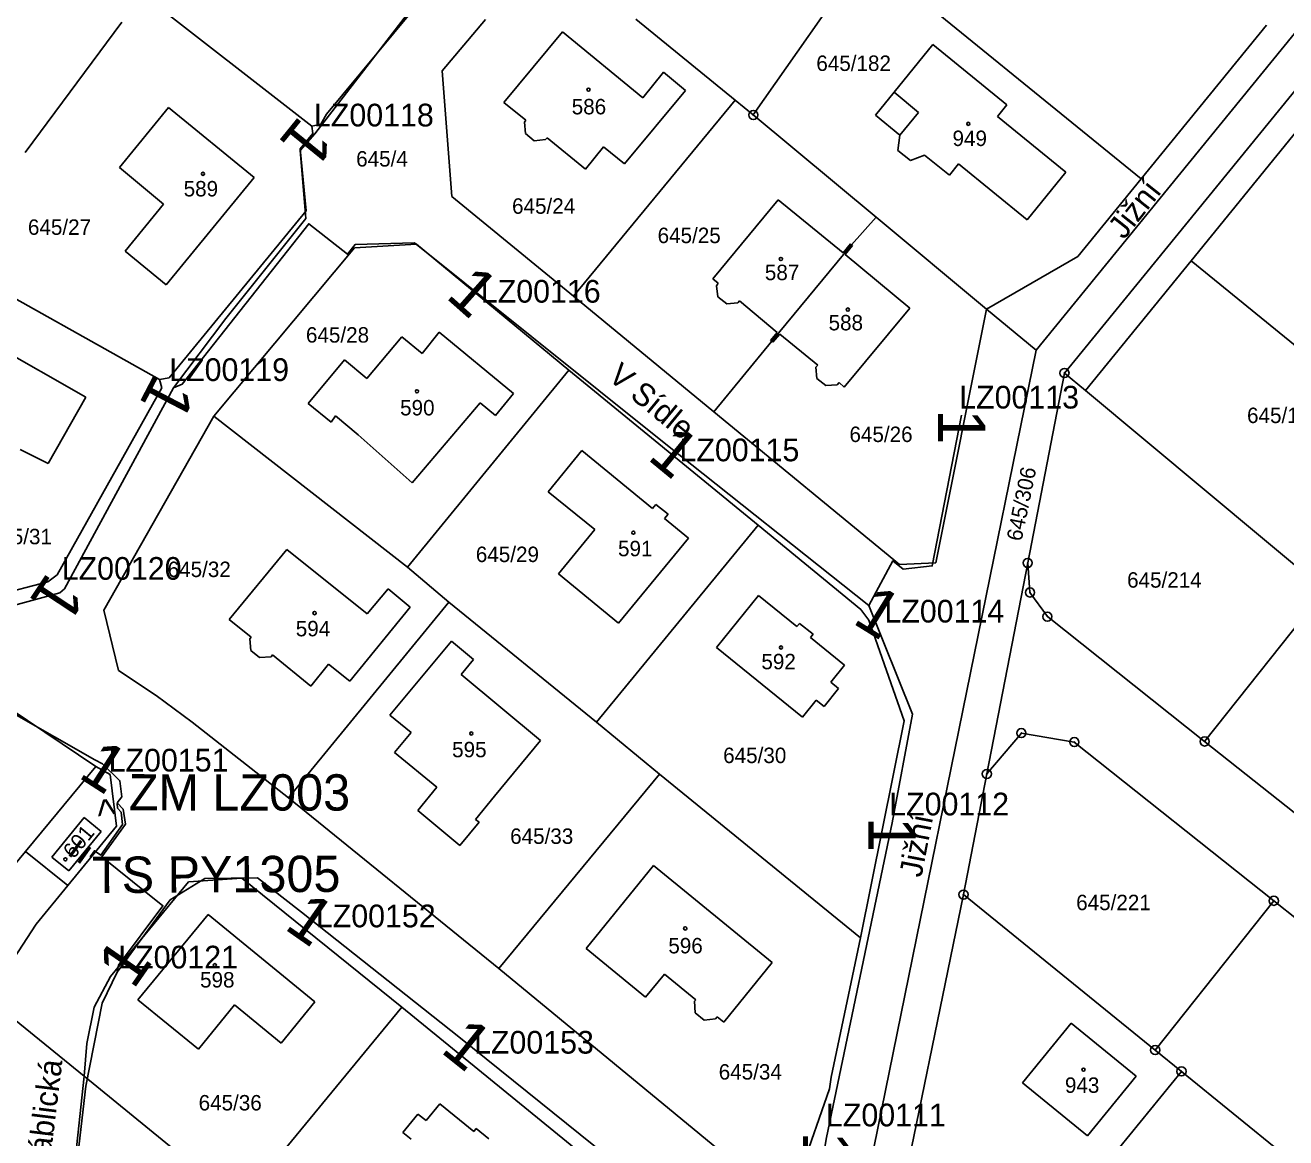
# Model space of a CAD drawing. Extents: x -738131 to -734179, y -1033447 to -1030078.
# Drawn here: x -735880.3 to -735741.5, y -1032698.6 to -1032576 of the extents above; entities that cross this region are included whole.
import ezdxf

# ---------------------------------------------------------------- set-up
doc = ezdxf.new("R2010")
doc.units = 0
for name, color, linetype in [('ftf_2010', 7, 'Continuous'), ('ftf_2060', 7, 'Continuous'), ('ftf_3010', 7, 'Continuous'), ('ftf_3010_ftf_3010_gtda_3015_gtda_3015_1', 7, 'Continuous'), ('ftf_3150', 7, 'Continuous'), ('ftf_3150_ftf_3150_gtda_3155_gtda_3155_1', 7, 'Continuous'), ('ftf_3160', 7, 'Continuous'), ('ftf_3160_ftf_3160_gtda_3165_gtda_3165_1', 7, 'Continuous'), ('ftf_nu', 7, 'Continuous'), ('Vrstva 1', 7, 'Continuous'), ('Vrstva 2', 7, 'Continuous'), ('Vrstva 4', 7, 'Continuous'), ('Vrstva 5', 7, 'Continuous'), ('Vrstva 8', 7, 'Continuous')]:
    doc.layers.add(name, color=color, linetype=linetype)

msp = doc.modelspace()

# ---------------------------------------------------------------- linework, layer by layer
at = {"layer": 'ftf_2010'}
for points in [[(-735833.85, -1032569.08), (-735848.46, -1032588)], [(-735864.01, -1032615.98), (-735858.25, -1032608.32), (-735849.42, -1032597.31), (-735850.04, -1032589.82), (-735848.46, -1032588)], [(-735864.01, -1032615.98), (-735863.04, -1032615.57), (-735849.11, -1032597.9), (-735844.85, -1032601.26), (-735844.01, -1032600.2), (-735837.47, -1032600), (-735831.94, -1032604.46)], [(-735831.94, -1032604.46), (-735809.79, -1032622.16)], [(-735876.03, -1032638.12), (-735864.01, -1032615.98)], [(-735777.21, -1032618.97), (-735780.45, -1032635.59), (-735783.63, -1032635.93), (-735784.8, -1032635.04), (-735787.44, -1032639.95)], [(-735809.79, -1032622.16), (-735787.44, -1032639.95)], [(-735899.61, -1032641.58), (-735899.03, -1032641.38), (-735886.29, -1032648.56), (-735883.11, -1032640.33), (-735876.51, -1032638.56), (-735876.03, -1032638.12)], [(-735787.44, -1032639.95), (-735782.6, -1032651.92), (-735784.87, -1032663.88)], [(-735899.61, -1032641.58), (-735872.69, -1032656.96)], [(-735872.69, -1032656.96), (-735871.81, -1032657.37), (-735869.91, -1032659.24), (-735869.7, -1032661.03), (-735870.21, -1032661.69)], [(-735870.21, -1032661.69), (-735869.54, -1032662.38), (-735869.3, -1032664.04), (-735871.9, -1032667.64), (-735868.54, -1032670.33), (-735865.18, -1032673.02), (-735870.05, -1032679.55), (-735870.2, -1032680.32)], [(-735792.09, -1032698.53), (-735784.87, -1032663.88)], [(-735870.2, -1032680.32), (-735864.37, -1032672.38), (-735860.55, -1032670), (-735854.75, -1032669.95), (-735849.92, -1032673.73)], [(-735832.6, -1032687.44), (-735849.92, -1032673.73)], [(-735870.2, -1032680.32), (-735871.88, -1032683.75), (-735873.65, -1032692.87), (-735875.34, -1032707.51), (-735877.04, -1032718.13)], [(-735813.21, -1032703.05), (-735832.6, -1032687.44)], [(-735792.09, -1032698.53), (-735792.3, -1032699.81), (-735782.31, -1032701.83), (-735783.9, -1032709.89), (-735780.53, -1032712.49)]]:
    msp.add_lwpolyline(points, dxfattribs=at)
at = {"layer": 'ftf_2060'}
msp.add_lwpolyline([(-735870.22, -1032661.74), (-735870.17, -1032662.25), (-735869.79, -1032662.71), (-735869.62, -1032664.07), (-735872.02, -1032667.44), (-735872.71, -1032666.96), (-735873.19, -1032667.63)], dxfattribs=at)
at = {"layer": 'Vrstva 1'}
for points in [[(-735700.24, -1032527.51), (-735768.99, -1032611.83)], [(-735765.88, -1032614.34), (-735697.13, -1032530.02)], [(-735787.81, -1032568.23), (-735800.15, -1032585.92)], [(-735787.81, -1032568.23), (-735757.44, -1032592.96)], [(-735834.19, -1032570.19), (-735847.14, -1032585.83)], [(-735867.41, -1032572.61), (-735848.77, -1032587.14)], [(-735829.66, -1032575.39), (-735834.43, -1032581.05)], [(-735802.16, -1032584.28), (-735813.08, -1032575.37)], [(-735869.69, -1032575.68), (-735880.36, -1032590.05)], [(-735821.16, -1032576.77), (-735827.63, -1032584.55)], [(-735812.32, -1032584.03), (-735821.16, -1032576.77)], [(-735743.64, -1032576.01), (-735757.44, -1032592.96)], [(-735784.64, -1032583.41), (-735780.38, -1032578.16)], [(-735780.38, -1032578.16), (-735772.24, -1032584.8)], [(-735834.43, -1032581.05), (-735833.35, -1032594.91)], [(-735810.05, -1032581.21), (-735812.32, -1032584.03)], [(-735810.05, -1032581.21), (-735807.61, -1032583.24)], [(-735807.61, -1032583.24), (-735814.32, -1032591.3)], [(-735786.69, -1032585.94), (-735784.64, -1032583.41)], [(-735869.97, -1032591.69), (-735864.55, -1032585.08)], [(-735864.55, -1032585.08), (-735855.12, -1032592.82)], [(-735827.63, -1032584.55), (-735825.19, -1032586.49)], [(-735802.16, -1032584.28), (-735819.96, -1032605.86)], [(-735800.15, -1032585.92), (-735802.16, -1032584.28)], [(-735772.24, -1032584.8), (-735773.27, -1032586.07)], [(-735847.79, -1032586.92), (-735847.14, -1032585.83)], [(-735825.19, -1032586.49), (-735825.35, -1032586.71)], [(-735800.15, -1032585.92), (-735786.61, -1032597.19)], [(-735784.02, -1032588.13), (-735786.69, -1032585.94)], [(-735773.27, -1032586.07), (-735765.72, -1032592.23)], [(-735850.05, -1032589.63), (-735848.68, -1032587.96)], [(-735848.77, -1032587.14), (-735847.79, -1032586.92)], [(-735848.68, -1032587.96), (-735848.77, -1032587.14)], [(-735825.35, -1032586.71), (-735825.25, -1032587.96)], [(-735825.25, -1032587.96), (-735824.28, -1032588.76)], [(-735751.92, -1032601.97), (-735740.24, -1032587.63)], [(-735824.28, -1032588.76), (-735823.04, -1032588.63)], [(-735823.04, -1032588.63), (-735822.84, -1032588.43)], [(-735818.65, -1032591.89), (-735822.84, -1032588.43)], [(-735816.66, -1032589.42), (-735818.65, -1032591.89)], [(-735814.32, -1032591.3), (-735816.66, -1032589.42)], [(-735784.25, -1032589.82), (-735784.02, -1032588.13)], [(-735849.38, -1032596.47), (-735850.05, -1032589.63)], [(-735782.85, -1032590.93), (-735784.25, -1032589.82)], [(-735781.29, -1032590.33), (-735782.85, -1032590.93)], [(-735778.56, -1032592.54), (-735781.29, -1032590.33)], [(-735865.12, -1032595.75), (-735869.97, -1032591.69)], [(-735777.55, -1032591.29), (-735778.56, -1032592.54)], [(-735770, -1032597.48), (-735777.55, -1032591.29)], [(-735765.72, -1032592.23), (-735770, -1032597.48)], [(-735855.12, -1032592.82), (-735864.81, -1032604.64)], [(-735757.44, -1032592.96), (-735764.4, -1032601.49)], [(-735819.96, -1032605.86), (-735833.35, -1032594.91)], [(-735869.34, -1032600.92), (-735865.12, -1032595.75)], [(-735797.41, -1032595.25), (-735804.61, -1032603.96)], [(-735790.25, -1032601.12), (-735797.41, -1032595.25)], [(-735864.48, -1032614.86), (-735849.38, -1032596.47)], [(-735789.33, -1032600.21), (-735786.61, -1032597.19)], [(-735786.61, -1032597.19), (-735774.46, -1032607.29)], [(-735844.06, -1032600.56), (-735859.56, -1032619.1)], [(-735837.26, -1032600.15), (-735844.06, -1032600.56)], [(-735820.48, -1032614.02), (-735837.26, -1032600.15)], [(-735798.12, -1032610.84), (-735789.33, -1032600.21)], [(-735789.44, -1032600.11), (-735790.25, -1032601.12)], [(-735789.23, -1032600.31), (-735790.05, -1032601.29)], [(-735789.33, -1032600.21), (-735789.44, -1032600.11)], [(-735789.33, -1032600.21), (-735789.23, -1032600.31)], [(-735864.81, -1032604.64), (-735869.34, -1032600.92)], [(-735790.05, -1032601.29), (-735782.92, -1032607.19)], [(-735774.46, -1032607.29), (-735764.4, -1032601.49)], [(-735751.92, -1032601.97), (-735763.57, -1032616.26)], [(-735751.92, -1032601.97), (-735718.51, -1032629.19)], [(-735865.54, -1032615.06), (-735887.57, -1032602.71)], [(-735804.61, -1032603.96), (-735804.01, -1032604.46)], [(-735804.01, -1032604.46), (-735804.21, -1032604.72)], [(-735804.21, -1032604.72), (-735804.06, -1032605.93)], [(-735804.48, -1032618.62), (-735819.96, -1032605.86)], [(-735804.06, -1032605.93), (-735803.08, -1032606.73)], [(-735803.08, -1032606.73), (-735801.85, -1032606.61)], [(-735801.67, -1032606.39), (-735801.85, -1032606.61)], [(-735801.67, -1032606.39), (-735797.52, -1032609.87)], [(-735782.92, -1032607.19), (-735790.13, -1032615.89)], [(-735774.46, -1032607.29), (-735780.06, -1032635.26)], [(-735774.46, -1032607.29), (-735768.99, -1032611.83)], [(-735836.63, -1032612.19), (-735834.74, -1032609.85)], [(-735834.74, -1032609.85), (-735826.55, -1032616.58)], [(-735797.52, -1032609.87), (-735798.24, -1032610.76)], [(-735798, -1032610.93), (-735797.24, -1032610.05)], [(-735793.06, -1032613.47), (-735797.24, -1032610.05)], [(-735883.86, -1032611.2), (-735873.65, -1032616.99)], [(-735838.86, -1032610.35), (-735842.7, -1032614.94)], [(-735838.86, -1032610.35), (-735836.63, -1032612.19)], [(-735798.12, -1032610.84), (-735804.48, -1032618.62)], [(-735798.24, -1032610.76), (-735798.12, -1032610.84)], [(-735798.12, -1032610.84), (-735798, -1032610.93)], [(-735845.19, -1032612.87), (-735849.17, -1032617.68)], [(-735842.7, -1032614.94), (-735845.19, -1032612.87)], [(-735768.99, -1032611.83), (-735797.93, -1032753.98)], [(-735820.48, -1032614.02), (-735838.24, -1032635.71)], [(-735799.63, -1032631.11), (-735820.48, -1032614.02)], [(-735793.26, -1032613.7), (-735793.06, -1032613.47)], [(-735793.14, -1032614.94), (-735793.26, -1032613.7)], [(-735769.93, -1032635.25), (-735765.88, -1032614.34)], [(-735765.88, -1032614.34), (-735763.57, -1032616.26)], [(-735865.54, -1032615.06), (-735864.48, -1032614.86)], [(-735865.29, -1032615.98), (-735865.54, -1032615.06)], [(-735792.15, -1032615.73), (-735793.14, -1032614.94)], [(-735790.91, -1032615.63), (-735792.15, -1032615.73)], [(-735790.71, -1032615.4), (-735790.91, -1032615.63)], [(-735790.13, -1032615.89), (-735790.71, -1032615.4)], [(-735873.65, -1032616.99), (-735877.82, -1032624.32)], [(-735865.29, -1032615.98), (-735876.83, -1032636.55)], [(-735826.55, -1032616.58), (-735828.55, -1032619.03)], [(-735763.57, -1032616.26), (-735737.19, -1032638.25)], [(-735849.17, -1032617.68), (-735846.65, -1032619.75)], [(-735830.25, -1032617.64), (-735837.71, -1032626.43)], [(-735828.55, -1032619.03), (-735830.25, -1032617.64)], [(-735804.48, -1032618.62), (-735784.05, -1032635.44)], [(-735859.56, -1032619.1), (-735871.68, -1032640.45)], [(-735859.56, -1032619.1), (-735838.24, -1032635.71)], [(-735846.65, -1032619.75), (-735846.15, -1032619.04)], [(-735846.15, -1032619.04), (-735843.67, -1032621.14)], [(-735843.67, -1032621.14), (-735837.71, -1032626.43)], [(-735877.82, -1032624.32), (-735880.88, -1032622.76)], [(-735819.02, -1032622.89), (-735822.73, -1032627.44)], [(-735811.24, -1032629.27), (-735819.02, -1032622.89)], [(-735822.73, -1032627.44), (-735817.6, -1032631.58)], [(-735810.88, -1032628.81), (-735811.24, -1032629.27)], [(-735809.53, -1032629.89), (-735810.88, -1032628.81)], [(-735817.41, -1032652.8), (-735799.63, -1032631.11)], [(-735809.92, -1032630.35), (-735809.53, -1032629.89)], [(-735807.27, -1032632.52), (-735809.92, -1032630.35)], [(-735788.31, -1032640.38), (-735799.63, -1032631.11)], [(-735817.6, -1032631.58), (-735821.61, -1032636.46)], [(-735851.53, -1032633.77), (-735857.86, -1032641.49)], [(-735851.53, -1032633.77), (-735842.67, -1032640.88)], [(-735815, -1032641.9), (-735807.27, -1032632.52)], [(-735784.05, -1032635.44), (-735780.06, -1032635.26)], [(-735769.93, -1032635.25), (-735774.43, -1032658.49)], [(-735769.68, -1032638.51), (-735769.93, -1032635.25)], [(-735877.85, -1032637.33), (-735876.83, -1032636.55)], [(-735833.69, -1032639.58), (-735838.24, -1032635.71)], [(-735821.61, -1032636.46), (-735815, -1032641.9)], [(-735883.52, -1032638.82), (-735877.85, -1032637.33)], [(-735840.38, -1032638.11), (-735842.67, -1032640.88)], [(-735837.94, -1032640.12), (-735840.38, -1032638.11)], [(-735804.21, -1032644.56), (-735799.59, -1032638.85)], [(-735799.59, -1032638.85), (-735795.35, -1032642.25)], [(-735767.76, -1032641.17), (-735769.68, -1032638.51)], [(-735737.19, -1032638.25), (-735750.44, -1032654.92)], [(-735871.68, -1032640.45), (-735870.05, -1032647.12)], [(-735851.36, -1032661.13), (-735833.69, -1032639.58)], [(-735844.6, -1032648.26), (-735837.94, -1032640.12)], [(-735817.41, -1032652.8), (-735833.69, -1032639.58)], [(-735787.43, -1032641.56), (-735788.31, -1032640.38)], [(-735857.86, -1032641.49), (-735855.47, -1032643.45)], [(-735795.35, -1032642.25), (-735795.05, -1032641.91)], [(-735795.05, -1032641.91), (-735793.56, -1032643.1)], [(-735787.43, -1032641.56), (-735783.54, -1032652.64)], [(-735750.44, -1032654.92), (-735767.76, -1032641.17)], [(-735855.47, -1032643.45), (-735855.61, -1032643.63)], [(-735793.56, -1032643.1), (-735793.85, -1032643.46)], [(-735793.85, -1032643.46), (-735790.11, -1032646.51)], [(-735855.61, -1032643.63), (-735855.5, -1032644.89)], [(-735855.5, -1032644.89), (-735854.54, -1032645.68)], [(-735833.4, -1032643.86), (-735840.17, -1032652.01)], [(-735833.4, -1032643.86), (-735830.96, -1032645.88)], [(-735794.75, -1032652.24), (-735804.21, -1032644.56)], [(-735854.54, -1032645.68), (-735853.25, -1032645.58)], [(-735853.25, -1032645.58), (-735853.1, -1032645.39)], [(-735853.1, -1032645.39), (-735848.88, -1032648.83)], [(-735830.96, -1032645.88), (-735832.34, -1032647.55)], [(-735870.05, -1032647.12), (-735865.91, -1032649.87)], [(-735848.88, -1032648.83), (-735846.92, -1032646.4)], [(-735846.92, -1032646.4), (-735844.6, -1032648.26)], [(-735832.34, -1032647.55), (-735823.6, -1032654.81)], [(-735790.11, -1032646.51), (-735791.61, -1032648.39)], [(-735790.77, -1032649.1), (-735792.35, -1032651.06)], [(-735791.61, -1032648.39), (-735790.77, -1032649.1)], [(-735872.56, -1032657.68), (-735883.85, -1032650.12)], [(-735865.91, -1032649.87), (-735861.95, -1032652.8)], [(-735793.24, -1032650.36), (-735794.75, -1032652.24)], [(-735792.35, -1032651.06), (-735793.24, -1032650.36)], [(-735861.95, -1032652.8), (-735851.36, -1032661.13)], [(-735840.17, -1032652.01), (-735837.84, -1032653.92)], [(-735810.47, -1032658.52), (-735817.41, -1032652.8)], [(-735788.36, -1032676.55), (-735783.54, -1032652.64)], [(-735837.84, -1032653.92), (-735839.68, -1032656.14)], [(-735774.43, -1032658.49), (-735770.62, -1032654)], [(-735770.62, -1032654), (-735764.8, -1032654.99)], [(-735823.6, -1032654.81), (-735828.64, -1032660.95)], [(-735764.8, -1032654.99), (-735742.82, -1032672.47)], [(-735725.07, -1032675.04), (-735750.44, -1032654.92)], [(-735839.68, -1032656.14), (-735835.02, -1032659.97)], [(-735880.32, -1032667.05), (-735872.56, -1032657.68)], [(-735828.17, -1032679.93), (-735810.47, -1032658.52)], [(-735810.47, -1032658.52), (-735788.36, -1032676.55)], [(-735777, -1032671.78), (-735774.43, -1032658.49)], [(-735835.02, -1032659.97), (-735837.11, -1032662.51)], [(-735828.17, -1032679.93), (-735851.36, -1032661.13)], [(-735828.64, -1032660.95), (-735830.75, -1032663.5)], [(-735832.48, -1032666.38), (-735837.11, -1032662.51)], [(-735877.41, -1032667.65), (-735873.86, -1032663.28)], [(-735873.86, -1032663.28), (-735871.98, -1032664.82)], [(-735830.35, -1032663.82), (-735832.48, -1032666.38)], [(-735830.75, -1032663.5), (-735830.35, -1032663.82)], [(-735871.98, -1032664.82), (-735875.53, -1032669.17)], [(-735889.95, -1032678.66), (-735880.32, -1032667.05)], [(-735875.53, -1032669.17), (-735877.41, -1032667.65)], [(-735818.56, -1032677.71), (-735811.15, -1032668.57)], [(-735811.15, -1032668.57), (-735798.06, -1032679.27)], [(-735856.48, -1032669.96), (-735862.36, -1032670.38)], [(-735856.48, -1032669.96), (-735838.85, -1032684.2)], [(-735870.95, -1032680.81), (-735862.36, -1032670.38)], [(-735784.76, -1032709.51), (-735777, -1032671.78)], [(-735777, -1032671.78), (-735755.89, -1032688.91)], [(-735755.89, -1032688.91), (-735742.82, -1032672.47)], [(-735742.82, -1032672.47), (-735718.72, -1032691.62)], [(-735860.19, -1032673.97), (-735867.93, -1032683.38)], [(-735848.44, -1032683.6), (-735860.19, -1032673.97)], [(-735788.36, -1032676.55), (-735791.56, -1032691.89)], [(-735818.56, -1032677.71), (-735812.02, -1032683.1)], [(-735803.39, -1032685.82), (-735798.06, -1032679.27)], [(-735872.75, -1032684.17), (-735870.95, -1032680.81)], [(-735799.36, -1032703.67), (-735828.17, -1032679.93)], [(-735812.02, -1032683.1), (-735809.94, -1032680.55)], [(-735809.94, -1032680.55), (-735806.48, -1032683.37)], [(-735867.93, -1032683.38), (-735861.27, -1032688.8)], [(-735852.16, -1032688.15), (-735848.44, -1032683.6)], [(-735806.48, -1032683.37), (-735806.61, -1032683.54)], [(-735806.61, -1032683.54), (-735806.55, -1032684.81)], [(-735883.1, -1032684.24), (-735873.85, -1032691.79)], [(-735873.56, -1032688.17), (-735872.75, -1032684.17)], [(-735861.27, -1032688.8), (-735857.28, -1032683.93)], [(-735857.28, -1032683.93), (-735852.16, -1032688.15)], [(-735838.85, -1032684.2), (-735856.66, -1032705.82)], [(-735817.92, -1032701.26), (-735838.85, -1032684.2)], [(-735806.55, -1032684.81), (-735805.56, -1032685.6)], [(-735804.3, -1032685.46), (-735804.12, -1032685.25)], [(-735804.12, -1032685.25), (-735803.39, -1032685.82)], [(-735805.56, -1032685.6), (-735804.3, -1032685.46)], [(-735770.52, -1032692.53), (-735765.15, -1032685.94)], [(-735765.15, -1032685.94), (-735757.98, -1032691.78)], [(-735873.85, -1032691.79), (-735873.56, -1032688.17)], [(-735755.89, -1032688.91), (-735752.99, -1032691.26)], [(-735873.85, -1032691.79), (-735876.63, -1032717.78)], [(-735856.66, -1032705.82), (-735873.85, -1032691.79)], [(-735791.56, -1032691.89), (-735791.77, -1032693.18)], [(-735774.61, -1032717.79), (-735752.99, -1032691.26)], [(-735757.98, -1032691.78), (-735763.35, -1032698.37)], [(-735752.99, -1032691.26), (-735735.91, -1032705.13)], [(-735791.77, -1032693.18), (-735794.88, -1032702.14)], [(-735763.35, -1032698.37), (-735770.52, -1032692.53)], [(-735834.69, -1032694.83), (-735836.19, -1032696.68)], [(-735830.94, -1032697.88), (-735834.69, -1032694.83)], [(-735837.09, -1032695.96), (-735838.75, -1032697.99)], [(-735836.19, -1032696.68), (-735837.09, -1032695.96)], [(-735830.94, -1032697.88), (-735830.67, -1032697.54)], [(-735830.67, -1032697.54), (-735829.29, -1032698.68)], [(-735838.75, -1032697.99), (-735837.84, -1032698.72)]]:
    msp.add_lwpolyline(points, dxfattribs=at)
at = {"layer": 'Vrstva 4'}
for points in [[(-735784.64, -1032583.41), (-735781.96, -1032585.64)], [(-735781.96, -1032585.64), (-735784.02, -1032588.13)], [(-735872.56, -1032657.68), (-735871, -1032658.55)], [(-735871, -1032658.55), (-735870.28, -1032664.24)], [(-735870.28, -1032664.24), (-735875.65, -1032670.8)], [(-735875.65, -1032670.8), (-735880.32, -1032667.05)], [(-735875.65, -1032670.8), (-735879.15, -1032675.06)], [(-735879.15, -1032675.06), (-735881.59, -1032678.84)]]:
    msp.add_lwpolyline(points, dxfattribs=at)
at = {"layer": 'Vrstva 5'}
for centre in [(-735818.3, -1032583.13), (-735776.47, -1032586.89), (-735860.76, -1032592.4), (-735797.11, -1032601.78), (-735789.74, -1032607.35), (-735837.19, -1032616.35), (-735813.36, -1032631.93), (-735848.47, -1032640.78), (-735797.1, -1032644.57), (-735831.21, -1032654.04), (-735875.92, -1032667.9), (-735807.65, -1032675.51), (-735859.46, -1032679.56), (-735763.78, -1032691.06)]:
    msp.add_circle(centre, 0.175, dxfattribs=at)
at = {"layer": 'Vrstva 8'}
for centre, radius in [((-735800.15, -1032585.92), 0.5), ((-735800.15, -1032585.92), 0.0303), ((-735765.88, -1032614.34), 0.5), ((-735765.88, -1032614.34), 0.0303), ((-735769.93, -1032635.25), 0.5), ((-735769.93, -1032635.25), 0.0303), ((-735769.68, -1032638.51), 0.5), ((-735769.68, -1032638.51), 0.0303), ((-735767.76, -1032641.17), 0.5), ((-735767.76, -1032641.17), 0.0303), ((-735770.62, -1032654), 0.5), ((-735770.62, -1032654), 0.0303), ((-735764.8, -1032654.99), 0.5), ((-735750.44, -1032654.92), 0.5), ((-735764.8, -1032654.99), 0.0303), ((-735750.44, -1032654.92), 0.0303), ((-735774.43, -1032658.49), 0.5), ((-735774.43, -1032658.49), 0.0303), ((-735777, -1032671.78), 0.5), ((-735777, -1032671.78), 0.0303), ((-735742.82, -1032672.47), 0.5), ((-735742.82, -1032672.47), 0.0303), ((-735755.89, -1032688.91), 0.5), ((-735755.89, -1032688.91), 0.0303), ((-735752.99, -1032691.26), 0.5), ((-735752.99, -1032691.26), 0.0303)]:
    msp.add_circle(centre, radius, dxfattribs=at)

# ---------------------------------------------------------------- texts
at = {"layer": 'ftf_3010'}
for rotation, p in [(230.893, (-735850.07, -1032585.86)), (318.4106, (-735834.15, -1032605.98)), (242.4362, (-735866.01, -1032614.2)), (270, (-735779.81, -1032618.32)), (320.5467, (-735811.94, -1032623.76)), (236.6337, (-735877.84, -1032636.15)), (328.2545, (-735789.36, -1032641.82)), (327.2351, (-735874.64, -1032658.8)), (270, (-735787.47, -1032663.23)), (325.0729, (-735851.94, -1032675.49)), (55.1966, (-735868.44, -1032682.34)), (321.395, (-735834.73, -1032689.06)), (270, (-735794.69, -1032697.88))]:
    msp.add_text('1', height=5.2, rotation=rotation, dxfattribs=at).set_placement(p)
at = {"layer": 'ftf_3010_ftf_3010_gtda_3015_gtda_3015_1'}
for s, p in [('LZ00118', (-735848.54, -1032587.18)), ('LZ00119', (-735864.48, -1032615.22)), ('LZ00113', (-735777.47, -1032618.25)), ('LZ00120', (-735876.32, -1032637.11)), ('LZ00112', (-735785.18, -1032663.06)), ('LZ00121', (-735870.1, -1032679.92)), ('LZ00111', (-735792.15, -1032697.31))]:
    msp.add_text(s, height=2.5, rotation=0, dxfattribs=at).set_placement(p)
for s, p in [('LZ00116', (-735830.16, -1032606.59)), ('LZ00115', (-735808.28, -1032624.06)), ('LZ00114', (-735785.71, -1032641.82)), ('LZ00151', (-735871.15, -1032658.23)), ('LZ00152', (-735848.33, -1032675.39)), ('LZ00153', (-735830.91, -1032689.3))]:
    msp.add_text(s, height=2.5, dxfattribs=at).set_placement(p)
at = {"layer": 'ftf_3150'}
msp.add_text('>', height=2.7, rotation=97.9419, dxfattribs=at).set_placement((-735870.03, -1032663.03))
at = {"layer": 'ftf_3150_ftf_3150_gtda_3155_gtda_3155_1'}
msp.add_text('ZM LZ003', height=4, rotation=359.9641, dxfattribs=at).set_placement((-735868.93, -1032662.52))
at = {"layer": 'ftf_3160'}
msp.add_text('=', height=3.3, rotation=54.532, dxfattribs=at).set_placement((-735873.77, -1032669.04))
at = {"layer": 'ftf_3160_ftf_3160_gtda_3165_gtda_3165_1'}
msp.add_text('TS PY1305', height=4, rotation=0.2894, dxfattribs=at).set_placement((-735872.97, -1032671.62))
at = {"layer": 'ftf_nu'}
for s, rotation, p in [('Jižní', 51.6208, (-735759.33, -1032599.73)), ('V Sídle', 320.5045, (-735816.28, -1032614.96)), ('Jižní', 78.9873, (-735781.64, -1032669.98)), ('Ďáblická', 82.9721, (-735877.8, -1032702.82))]:
    msp.add_text(s, height=2.5, rotation=rotation, dxfattribs=at).set_placement(p)
at = {"layer": 'Vrstva 2'}
for s, p in [('645/182', (-735793.21, -1032581.07)), ('586', (-735820.15, -1032585.85)), ('949', (-735778.21, -1032589.34)), ('645/4', (-735843.89, -1032591.6)), ('589', (-735862.89, -1032594.89)), ('645/24', (-735826.72, -1032596.8)), ('645/27', (-735880.04, -1032599.12)), ('645/25', (-735810.69, -1032600.03)), ('587', (-735798.88, -1032604.11)), ('588', (-735791.86, -1032609.64)), ('645/28', (-735849.42, -1032610.99)), ('590', (-735839.05, -1032619.01)), ('645/170', (-735745.77, -1032619.85)), ('645/26', (-735789.56, -1032621.94)), ('645/31', (-735884.35, -1032633.2)), ('645/29', (-735830.71, -1032635.16)), ('591', (-735815.05, -1032634.52)), ('645/32', (-735864.65, -1032636.81)), ('645/214', (-735758.98, -1032637.98)), ('594', (-735850.54, -1032643.34)), ('592', (-735799.26, -1032646.97)), ('595', (-735833.32, -1032656.66)), ('645/30', (-735803.47, -1032657.3)), ('645/33', (-735826.93, -1032666.2)), ('645/221', (-735764.59, -1032673.5)), ('596', (-735809.51, -1032678.26)), ('598', (-735861.08, -1032682.02)), ('645/34', (-735803.96, -1032692.16)), ('943', (-735765.83, -1032693.62)), ('645/36', (-735861.24, -1032695.56))]:
    msp.add_text(s, height=1.7, dxfattribs=at).set_placement(p)
for s, rotation, p in [('645/306', 78.518, (-735770.61, -1032632.94)), ('601', 50.6553, (-735875.01, -1032667.95))]:
    msp.add_text(s, height=1.7, rotation=rotation, dxfattribs=at).set_placement(p)

doc.saveas('drawing.dxf')
